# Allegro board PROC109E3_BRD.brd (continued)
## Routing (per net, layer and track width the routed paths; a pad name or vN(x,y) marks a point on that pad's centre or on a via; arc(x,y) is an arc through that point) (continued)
PRG1_IEP0_EDC_LATCH_IN0: length 33.4
  TOP w0.102: U18.Y4 86.67,27.08 87.14,27.08 87.58,26.65 87.58,26.64 87.74,26.49
  TOP w0.135: v1(98.73,24.18) 98.15,24.77 89.46,24.77 89.42,24.8 87.74,26.49
  BOTTOM w0.135: v1(98.73,24.18) 98.47,23.92 98.47,19.39 99.01,18.85 109.02,18.85 J5.8
PRG1_IEP0_EDC_LATCH_IN1: length 53.4
  TOP w0.102: v2(85.93,32.38) 85.41,31.86 U18.V13
  L03_SIG1 w0.102: v2(85.93,32.38) 86.65,32.38 87.44,33.17 87.74,33.17
  L03_SIG1 w0.121: 87.74,33.17 98.72,33.17 100.65,31.24 104.39,31.24 105.35,32.2 105.38,32.2 105.63,32.45 105.63,32.48 108.51,35.35 114.45,35.35 v1(114.88,35.79)
  BOTTOM w0.135: J5.12 116.95,18.49 114.88,20.55 v1(114.88,35.79)
PRG1_IEP0_EDC_SYNC_OUT0: length 33.5
  TOP w0.102: v2(85.36,26.82) 85.31,26.86 U18.U3
  L03_SIG1 w0.121: v2(85.36,26.82) 85.89,26.29 87.71,26.29 88.32,25.68 v1(98.73,25.68)
  BOTTOM w0.135: v1(98.73,25.68) 98.2,25.15 98.2,19.12 99.01,18.31 100.15,18.31 101.04,17.42 107.9,17.42 J5.6
PRG1_IEP0_EDC_SYNC_OUT1: length 36.2
  TOP w0.102: U18.T2 84.11,26.08 84.11,25.64 84.41,25.34 84.41,25.02
  TOP w0.135: 84.41,25.02 84.41,24.81 86.44,22.78 86.44,21.46 88.29,19.61 v1(99.01,19.61)
  BOTTOM w0.135: J5.10 110.8,19.61 v1(99.01,19.61)
PRG1_MDIO0_MDC: length 102.9
  TOP w0.102: U18.W1 86.23,25.53
  TOP w0.135: U7.42 139.68,43.77 v1(139.67,43.76) ; 86.23,25.53 87.88,23.88 91.39,23.88 v1(91.92,23.34) ; U19.42 v1(139.68,24.62)
  L03_SIG1 w0.121: v1(139.68,24.62) 142.04,26.97 142.04,31.04 141.4,31.67 138.18,31.67 137.69,31.19 137.69,25.73 138.61,24.82 138.61,21.01 137.72,20.12 133.08,20.12 132.02,21.18 100.07,21.18 97.48,23.77 92.35,23.77 v1(91.92,23.34)
  BOTTOM w0.135: v1(139.67,43.76) 139.99,43.45 139.99,42.38 139.52,41.91 138.66,41.91 136.42,39.67 136.42,27.88 v1(139.68,24.62)
PRG1_MDIO0_MDIO: length 88.5
  TOP w0.102: U18.V2 85.39,25.45 85.41,25.44
  TOP w0.114: 85.83,25.02 85.41,25.44
  TOP w0.135: R135.2 139.44,23.4 v1(139.42,23.42) 139.18,23.66 U19.41 ; v1(89.74,22.86) 87.99,22.86 85.83,25.02 ; v1(139.42,42.65) 139.42,43.09 139.18,43.33 U7.41
  L03_SIG1 w0.121: v1(89.74,22.86) 90.47,22.12 91.87,22.12 92.42,22.68 97.85,22.68 100.45,20.07 111.82,20.07 112.27,20.52 131.72,20.52 132.74,19.51 138.07,19.51 139.42,20.85 v1(139.42,23.42)
  BOTTOM w0.135: v1(139.42,23.42) 136.15,26.69 136.15,39.78 139.01,42.65 v1(139.42,42.65)
PRG1_RGMII1_RD0: length 25.9
  TOP w0.102: v2(85.93,26.82) 85.93,26.82 85.93,26.82 U18.V4
  L03_SIG1 w0.121: v1(100.63,26.01) 101.08,26.01 101.19,25.89 101.19,25.55 101.07,25.43 99.8,25.43 99.11,26.11 88.52,26.11 87.81,26.82 v2(85.93,26.82)
  BOTTOM w0.135: v1(100.63,26.01) 100.63,25.41 100.85,25.2 101.47,25.2 101.68,25.41 101.68,26.06 104.45,28.84 U40.29
PRG1_RGMII1_RD1: length 25.9
  TOP w0.102: v2(85.93,27.38) 85.89,27.41 U18.W5
  L03_SIG1 w0.121: v1(102.59,25.86) 103.56,24.89 103.56,24.61 103.25,24.31 102.92,24.31 101.96,25.27 101.96,25.65 101.18,26.43 88.95,26.43 88.92,26.47 88.77,26.47 87.82,27.38 v2(85.93,27.38)
  BOTTOM w0.135: U40.27 104.57,27.84 v1(102.59,25.86)
PRG1_RGMII1_RD2: length 25.9
  TOP w0.102: 87.74,26.87 87.24,27.36 U18.AA4
  TOP w0.135: 87.74,26.87 89.54,25.07 103.66,25.07 103.89,24.84 103.89,24.03 103.62,23.76 102.7,23.76 v1(102.26,24.21)
  BOTTOM w0.135: v1(102.26,24.21) 104.89,26.84 U40.25
PRG1_RGMII1_RD3: length 25.9
  TOP w0.102: U18.Y5 86.67,28.14 87.23,28.14 87.56,27.81
  TOP w0.135: 87.56,27.81 89.64,25.73 96.52,25.73 97.23,26.44 106.27,26.44 106.4,26.31 106.4,24.9 106.27,24.77 105.54,24.77 105.32,24.99 v1(105.32,25.84)
  BOTTOM w0.135: U40.23 v1(105.32,25.84)
PRG1_RGMII1_RX_CTL: length 25.9
  TOP w0.102: 87.74,27.25 87.13,27.86 U18.AA5
  TOP w0.135: v1(105.21,24.18) 104.04,25.35 100.23,25.35 99.47,26.11 97.66,26.11 96.95,25.4 89.59,25.4 87.74,27.25
  BOTTOM w0.135: U40.21 107.25,24.07 106.17,22.99 104.78,22.99 104.65,23.12 104.65,24.07 104.76,24.18 v1(105.21,24.18)
PRG1_RGMII1_RXC: length 26
  TOP w0.102: 87.74,25.6 87.17,26.16 87.17,26.48 87.01,26.64 86.67,26.64 U18.Y2
  TOP w0.135: 87.74,25.6 89.18,24.16 96.49,24.16 97.66,22.99 102.97,22.99 v1(103.68,22.28)
  BOTTOM w0.135: v1(103.68,22.28) 104.17,21.79 106.07,21.79 108.25,23.97 U40.19
PRG1_RGMII1_TD0: length 37.6
  TOP w0.102: U18.V5 84.98,27.86 v2(84.93,27.91)
  L03_SIG1 w0.121: v1(98.76,27.37) 98.57,27.55 88.76,27.55 88.14,28.16 85.19,28.16 v2(84.93,27.91)
  BOTTOM w0.135: U40.41 108.25,34.48 106.35,36.37 105.99,36.37 104.9,37.47 103.2,37.47 99.49,33.76 99.49,31.61 99.36,31.47 98.51,31.47 98.37,31.34 98.37,31.07 98.51,30.93 99.36,30.93 99.49,30.8 99.49,30.53 99.36,30.4 98.51,30.4 98.37,30.26 98.37,29.99 98.51,29.86 99.35,29.86 99.59,29.62 99.59,28.21 v1(98.76,27.37)
PRG1_RGMII1_TD1: length 37.7
  TOP w0.102: 86.21,25.02 85.61,25.61 85.61,26.08 U18.W2
  TOP w0.135: v1(100.56,22.3) 100.24,22.62 91.73,22.62 90.75,23.6 87.63,23.6 86.64,24.59 86.64,24.59 86.21,25.02
  BOTTOM w0.135: U40.39 107.25,34.29 107.24,34.29 105.92,35.61 102.06,35.61 101.13,34.68 101.13,33.69 100.1,32.66 100.1,22.76 v1(100.56,22.3)
PRG1_RGMII1_TD2: length 37.6
  TOP w0.102: U18.V6 85.39,28.78 v2(85.36,28.82)
  L03_SIG1 w0.121: v2(85.36,28.82) 85.73,28.45 88.34,28.45 88.98,27.81 100.24,27.81 v1(100.63,27.41)
  BOTTOM w0.135: v1(100.63,27.41) 101.22,27.41 101.38,27.57 101.38,27.98 101.17,28.19 100.61,28.19 100.47,28.33 100.47,28.6 100.61,28.73 101.21,28.73 101.35,28.87 101.35,29.14 101.21,29.27 100.61,29.27 100.47,29.4 100.47,29.67 100.61,29.81 101.06,29.81 101.19,29.94 101.19,30.21 101.06,30.35 100.61,30.35 100.47,30.48 100.47,30.75 100.61,30.89 101.21,30.89 101.35,31.02 101.35,31.29 101.21,31.42 100.61,31.42 100.47,31.56 100.47,31.83 100.61,31.96 101.21,31.96 101.4,32.15 101.4,34.54 101.9,35.05 104.27,35.05 104.73,34.59 104.92,34.59 105.5,35.16 105.77,35.16 105.94,34.98 105.94,34.72 105.18,33.96 105.18,33.77 105.61,33.34 U40.38
PRG1_RGMII1_TD3: length 37.7
  TOP w0.102: U18.AA7 87.65,28.86 87.74,28.77
  TOP w0.135: 87.74,28.77 89.84,26.67 95.68,26.67 97.22,28.2 102.04,28.2 103.3,29.46 103.3,30.02 105.23,31.95 106.17,31.95 106.83,31.29 106.83,29.59 107.14,29.29 109.73,29.29 110.08,29.64 110.08,31.7 109.73,32.05 106.73,32.05 106.16,32.62 v1(105.21,32.62)
  BOTTOM w0.135: v1(105.21,32.62) 105.21,32.36 105.36,32.21 105.61,32.21 105.74,32.34 U40.36
PRG1_RGMII1_TX_CTL: length 37.6
  TOP w0.102: 87.74,28.39 87.57,28.56 86.69,28.56 U18.Y7
  TOP w0.135: 87.74,28.39 89.79,26.34 95.96,26.34 97.54,27.91 102.41,27.91 103.26,27.07 106.37,27.07 106.56,27.26 106.56,27.63 106.43,27.76 104.71,27.76 104.52,27.95 104.52,28.19 104.66,28.33 106.43,28.33 106.56,28.46 106.56,28.7 106.4,28.86 104.73,28.86 104.6,29 104.6,29.24 104.73,29.38 106.43,29.38 106.56,29.51 106.56,29.78 106.43,29.92 105.39,29.92 105.26,30.05 105.26,30.32 105.39,30.45 106.16,30.45 106.3,30.59 106.3,31.2 106.16,31.34 v1(105.32,31.34)
  BOTTOM w0.135: U40.34 v1(105.32,31.34)
PRG1_RGMII1_TXC: length 30.7
  L03_SIG1 w0.121: v1(92.38,27.13) 92.82,27.13 93,26.94 101.71,26.94 102.03,26.62 103.2,26.62 103.34,26.77 103.34,26.94 102.95,27.33 v1(102.11,27.33)
  BOTTOM w0.135: R286.2 90.06,24.5 90.35,24.21 92.41,24.21 93.17,24.97 93.17,26.34 v1(92.38,27.13) ; v1(102.11,27.33) 101.79,27.65 101.79,28.08 101.93,28.22 102.91,28.22 103.05,28.35 103.05,28.69 102.91,28.82 101.93,28.82 101.79,28.96 101.79,29.53 102.74,30.48 104.9,30.48 105.05,30.34 U40.32
PRG_CPSW_RGMII1_MUX_SEL: length 49.5
  TOP w0.102: 87.2,36.7 86.73,36.24 86.37,36.24 86.11,35.98 86.11,35.64 U18.Y20
  TOP w0.135: R62.1 97.34,43.87 v1(97.33,43.87) 96.76,43.87 94.2,41.3 91.8,41.3 87.2,36.7
  L03_SIG1 w0.121: v1(110.36,41.57) 109.97,41.17 107.93,41.17 105.15,43.94 97.41,43.94 v1(97.33,43.87)
  BOTTOM w0.135: U40.10 110.49,28.84 110.74,29.08 110.74,29.08 ; U40.9 110.49,29.34 110.74,29.08 ; 110.74,29.08 111.05,29.08 111.43,28.7 R250.2 112.03,29.1 112.24,29.31 112.95,29.31 113.47,29.82 113.47,34.36 110.36,37.47 v1(110.36,41.57)
QSPI_RST_N: length 3.7
  TOP w0.135: U2.3 78.51,49.28 v1(78.49,49.25)
  BOTTOM w0.135: v1(78.49,49.25) 77.64,49.25 U31.4
R_BP_CONN_1_PORZ: length 3
  TOP w0.135: R4.1 R8.2 27.78,57.12 27.94,57.29 U1.3
R_BP_CONN_2_PORZ: length 3.2
  TOP w0.135: R2.2 R3.1 U1.6
SENCE3_IP: length 4
  BOTTOM w0.135: U27.8 20.24,54.08 21.37,52.95 R188.2
SOC_ADC0_AIN0: length 62.4
  TOP w0.102: 80.39,36.7 U18.H21
  TOP w0.135: R142.1 R143.2 43.65,20.78 45.17,22.3 51.59,22.3 v1(52.78,23.49) ; 80.39,36.7 80.39,38.5 79.96,38.94 79.96,43.05 78.11,44.91 72.39,44.91 71.56,44.08 67.73,44.08 67.21,43.56 64.41,43.56 63.63,42.77 v1(63.63,41.76) 63.63,41.1 C28.1
  BOTTOM w0.135: v1(52.78,23.49) 55.41,26.12 55.41,34.98 62.18,41.76 v1(63.63,41.76)
SOC_ADC0_AIN1: length 48.1
  TOP w0.102: U18.F19 79.79,34.86 v2(79.83,34.89)
  TOP w0.135: v1(58.72,23.39) 57.84,22.51 57.84,21.26 57.37,20.78 R153.1 R152.2
  L03_SIG1 w0.102: 79.83,35.39 v2(79.83,34.89)
  L03_SIG1 w0.121: 79.83,35.39 79.38,35.84 79.38,37.3 77.83,38.84 74.27,38.84 73.65,39.47 73.65,40.03 72.03,41.66 v1(69.14,41.66)
  BOTTOM w0.135: v1(58.72,23.39) 58.72,24.08 60.78,26.14 60.78,29.72 61.33,30.26 61.33,39 61.87,39.54 66.21,39.54 68.33,41.66 v1(69.14,41.66) 70.62,43.13 C118.1
SOC_ADC0_AIN2: length 59.1
  TOP w0.102: U18.F21 79.2,36.06 79.2,36.1 78.7,36.6 78.7,36.7
  TOP w0.135: v1(67.87,42.34) 68.53,43 72.36,43 73.19,43.83 77.66,43.83 78.7,42.78 78.7,36.7 ; R144.2 R145.1 46.39,20.78 47.58,21.97 52.55,21.97 v1(53.85,23.27)
  BOTTOM w0.135: C110.1 67.61,43.05 67.87,42.79 v1(67.87,42.34) 66.31,40.78 62.35,40.78 59.94,38.38 59.94,37.29 59.51,36.86 59.51,26.76 56.83,24.08 56.41,24.08 55.28,22.95 54.17,22.95 v1(53.85,23.27)
SOC_ADC0_AIN3: length 56.6
  TOP w0.102: 78.97,36.7 78.97,36.68 79.67,35.98 79.67,35.64 U18.F20
  TOP w0.135: R146.2 R147.1 49.14,20.78 50.05,21.7 53.22,21.7 v1(54.91,23.39) ; v1(66.27,42.52) 67.36,42.52 68.11,43.27 72,43.27 72.83,44.1 77.77,44.1 78.97,42.9 78.97,36.7
  BOTTOM w0.135: C108.1 66.11,42.68 v1(66.27,42.52) 66.27,42.44 64.88,41.05 62.24,41.05 58.22,37.03 58.22,26.7 v1(54.91,23.39)
SOC_ADC0_AIN4: length 64.1
  TOP w0.102: U18.H20 80.08,35.68 80.08,36.3 79.68,36.7
  TOP w0.135: R148.2 R149.1 51.88,20.78 52.51,21.41 54.01,21.41 55.99,23.39 v1(56.44,23.39) ; 79.68,36.7 79.53,36.86 79.53,37.01 79.53,43.1 77.99,44.64 72.5,44.64 71.67,43.81 67.84,43.81 67.31,43.28 64.68,43.28 64.26,42.87 v1(64.26,42.42) 64.26,41.94 65.14,41.05 C33.1
  BOTTOM w0.135: v1(56.44,23.39) 55.63,22.58 52.76,22.58 52.2,23.14 52.2,24.08 52.76,24.64 52.76,32.71 62.46,42.42 v1(64.26,42.42)
SOC_ADC0_AIN5: length 50.5
  TOP w0.102: 78.44,36.7 78.44,36.58 78.89,36.12 U18.E21
  TOP w0.135: R150.2 R151.1 54.62,20.78 55.99,22.15 56.72,22.15 57.45,22.89 v1(57.45,23.39) ; v1(68.86,42.57) 72.42,42.57 73.41,43.56 77.55,43.56 78.44,42.67 78.44,36.7
  BOTTOM w0.135: C117.1 69.11,42.82 v1(68.86,42.57) 66.8,40.51 62.46,40.51 61.06,39.11 61.06,30.65 60.5,30.1 60.5,26.44 v1(57.45,23.39)
SOC_ADC0_AIN6: length 58.2
  TOP w0.102: U18.G20 79.88,35.38 79.88,36.1 79.27,36.7
  TOP w0.135: 79.27,36.7 79.24,36.73 79.24,43.01 77.88,44.37 72.61,44.37 71.79,43.54 67.95,43.54 67.41,43 65.77,43 65.28,42.51 v1(65.28,42.06) 65.82,41.52 66.18,41.52 66.65,41.05 C35.1 ; R154.2 R155.1 60.3,21.01 60.3,22.73 58.57,24.46 v1(54.97,24.46)
  BOTTOM w0.135: v1(65.28,42.06) 64.54,41.33 62.13,41.33 55.68,34.87 55.68,25.17 v1(54.97,24.46)
SOC_ADC0_AIN7: length 51.7
  TOP w0.102: 78.16,36.7 78.16,36.57 78.58,36.15 78.58,35.68 U18.E20
  TOP w0.135: C36.1 69.37,41.05 v1(70.43,42.11) 72.67,42.11 73.85,43.29 77.44,43.29 78.16,42.56 78.16,36.71 78.16,36.7 ; v1(59.99,24.64) 60.91,24.64 63.22,22.33 63.22,21.19 R157.1 R156.2
  BOTTOM w0.135: v1(70.43,42.11) 70.12,41.8 69.94,41.8 67.41,39.27 61.98,39.27 61.6,38.89 61.6,37.24 62.36,36.48 62.36,30.35 61.77,29.77 61.77,26.42 v1(59.99,24.64)
SOC_CLKIN: length 5.6
  TOP w0.102: U18.D20 78.38,35.38 78.38,36.06 77.8,36.64 77.8,36.7
  TOP w0.135: 77.8,36.7 77.24,37.26 77.24,39.67 77.42,39.86 U11.4
SOC_CLKIN_BUFF: length 66.2
  TOP w0.135: v1(76.12,41.02) U11.2 ; R46.2 v1(115.27,47.37)
  L03_SIG1 w0.121: v1(76.12,41.02) 76.12,42.66 70.14,48.65 70.14,49.53 70.39,49.78 71.76,49.78 72.44,49.1 77.34,49.1 77.61,48.83 79.15,48.83 79.65,49.33 82.04,49.33 83.59,47.77 83.59,47.19 85.75,45.03 87.28,45.03 88.01,44.3 88.01,43.77 88.34,43.44 90.14,43.44 90.99,44.29 91.54,44.29 91.87,43.96 91.87,43.87 92.56,43.19 93.12,43.19 93.57,43.64 93.57,44.2 93.92,44.54 96.69,44.54 97.94,45.79 104.7,45.79 106.93,43.57 109.95,43.57 112.95,46.57 114.46,46.57 v1(115.27,47.37)
SOC_CLKIN_BUFF_R: length 2.6
  TOP w0.135: R46.1 116.93,47.96 117.16,48.19 U6.3
SOC_CPSW_RGMII1_TXC: length 1.5
  TOP w0.102: v2(85.93,31.32) 85.93,31.83 U18.W13
  BOTTOM w0.135: R287.1 86.21,31.04 v2(85.93,31.32)
SOC_EMU0: length 58.5
  TOP w0.102: U18.C5 77.89,27.41 v2(77.86,27.38)
  TOP w0.135: U16.5 28.79,35.14 29.69,34.24 29.69,33.27 30.76,32.21 v1(31.39,32.21)
  L03_SIG1 w0.121: v2(77.86,27.38) 74.67,24.19 73.37,24.19 71.59,25.96 69.42,25.96 66.85,28.53 65.92,28.53 65.18,29.27 65.18,30.32 63.84,31.66 44.99,31.66 44.2,30.86 39.15,30.86 38.35,31.66 37.25,31.66 36.7,32.21 v1(31.39,32.21)
SOC_EMU1: length 66
  TOP w0.102: U18.B3 77.11,27.14 76.77,27.14
  TOP w0.114: 76.77,27.14 76.34,26.71 76.34,25.97 76.05,25.68
  TOP w0.135: v1(32,35.53) 31.61,35.14 U16.4 ; 76.05,25.68 73.92,23.55 73.92,20.02 v1(73.56,19.66)
  L03_SIG1 w0.121: v1(73.56,19.66) 73.56,21.89 72.06,23.39 72.06,24.43 70.79,25.7 69.27,25.7 66.69,28.28 65.81,28.28 64.9,29.19 64.9,30.24 63.74,31.4 45.24,31.4 44.2,30.35 39.15,30.35 38.1,31.4 37.13,31.4 36.79,31.74 31.2,31.74 30.89,32.05 30.89,34.42 v1(32,35.53)
SOC_I2C0_SCL: length 223.6
  TOP w0.135: U17.6 64.69,35.84 65.48,36.63 66.75,36.63 v1(67.21,36.17) 67.84,35.53 R93.1 ; v1(147.02,19.86) 146.3,20.57 R141.1
  L03_SIG1 w0.121: v1(67.21,36.17) 67.21,37.48 65.17,39.52 62.79,39.52 61.32,41 57,41 54.33,43.66 45.87,43.66 45.21,44.32 42.07,44.32 41.64,43.89 39.04,43.89 v1(38.05,44.88) ; v1(147.02,19.86) 147.02,20.3 153.75,27.04 v1(153.75,41.27) 153.75,48.96 v1(156.82,52.03)
  BOTTOM w0.135: R237.2 67.23,36.2 v1(67.21,36.17) ; v1(38.05,44.88) 38.05,45.7 37.52,46.23 37.52,47.85 40.44,50.77 40.44,53.09 38.66,54.86 38.66,59.64 40.06,61.04 71.71,61.04 74.35,58.4 82.48,58.4 83.61,59.54 83.61,60.33 86.06,62.78 136.69,62.78 147.43,52.03 v1(156.82,52.03) ; U35.15 v1(153.75,41.27)
SOC_I2C0_SCL_BP: length 27.8
  TOP w0.135: J5.17 125.78,14.67 129.32,14.67 132.2,11.79 139.93,11.79 141.78,13.64 141.78,14.91 143.43,16.56 143.43,19.4 144.57,20.54 R141.2
SOC_I2C0_SCL_RC: length 9.2
  TOP w0.102: U18.B16 77.38,33.38 76.23,33.38 76.16,33.44 76.05,33.44
  TOP w0.135: R93.2 C47.1 69.94,34.12 70.18,33.88 72.85,33.88 73.29,33.44 76.05,33.44
SOC_I2C0_SDA: length 228
  TOP w0.135: R97.1 68.96,32.68 67.49,34.15 67.49,35.05 66.37,36.17 v1(65.91,36.17) 65.6,36.17 65.34,35.92 U17.5 ; R158.1 v1(146.23,19.08)
  L03_SIG1 w0.121: v1(158.8,51.28) 156.13,48.62 v1(156.13,41.27) 156.13,26.6 148.6,19.08 v1(146.23,19.08) ; v1(65.91,36.17) 65.91,38.42 65.06,39.27 62.59,39.27 61.27,40.59 56.82,40.59 55.04,42.37 39.4,42.37 v1(37.91,43.86)
  BOTTOM w0.135: v1(65.91,36.17) R238.2 ; v1(37.91,43.86) 38.48,44.42 38.48,45.92 37.8,46.61 37.8,47.75 40.74,50.7 40.74,53.4 38.93,55.22 38.93,59.4 40.3,60.77 71.55,60.77 74.19,58.14 82.62,58.14 83.88,59.4 83.88,60.22 86.18,62.51 136.5,62.51 147.73,51.28 v1(158.8,51.28) ; U35.2 v1(156.13,41.27)
SOC_I2C0_SDA_BP: length 24.8
  TOP w0.135: R158.2 144.52,17.04 143.16,15.67 143.16,12.7 141.36,10.9 129.67,10.9 J5.19
SOC_I2C0_SDA_RC: length 9.9
  TOP w0.102: U18.B15 77.08,33.17 76.05,33.17
  TOP w0.135: v1(70.03,33.41) 70.03,33.41 69.94,33.32 R97.2 70.22,32.36 70.69,32.36 71.88,33.55 72.79,33.55 73.17,33.17 76.05,33.17
  BOTTOM w0.135: v1(70.03,33.41) 70.03,33.43 70.04,33.43 C161.1
SOC_I2C1_SCL: length 135.5
  TOP w0.102: U18.A17 76.7,34.06 76.07,34.06 76.05,34.04
  TOP w0.135: R88.2 v1(69.55,37.11) 69.9,36.75 70.08,36.75 72.06,34.77 72.09,34.77 72.1,34.76 72.91,34.76 73.63,34.04 76.05,34.04 ; v1(42.72,35.59) 41.81,34.67 41.81,22.12 39.17,19.48 39.17,12.17 39.89,11.45 59.05,11.45 J1.17 ; U9.2 8.08,44.51 v1(7.42,45.16)
  L03_SIG1 w0.121: v1(69.55,37.11) 69.55,35.92 69.01,35.38 64.83,35.38 62.88,37.33 62.03,37.33 61.19,38.18 58.1,38.18 57.33,37.41 57.33,34.62 56.87,34.16 56.03,34.16 55.45,34.75 55.45,35.41 54.66,36.19 43.33,36.19 v1(42.72,35.59) 42.04,35.59 39.65,37.97 39.65,39.59 36.58,42.66 32.55,42.66 31.15,41.26 27.53,41.26 26.41,42.37 19.13,42.37 18.82,42.06 10.52,42.06 v1(7.42,45.16)
SOC_I2C1_SDA: length 138.9
  TOP w0.102: 76.05,34.64 77.11,34.64 U18.B18
  TOP w0.135: J1.19 61.32,11.18 39.78,11.18 38.86,12.09 38.86,19.69 41.38,22.2 41.38,35.13 v1(42.77,36.53) ; U9.3 8.34,45.16 v1(8.34,45.16) ; 76.05,34.64 75.77,34.64 75.11,35.31 72.29,35.31 70.33,37.26 70.33,37.44 70,37.77 70,38.1 v1(69.6,38.51) R82.2
  L03_SIG1 w0.121: v1(69.6,38.51) 69.09,38 69.09,35.97 68.78,35.66 64.91,35.66 62.98,37.59 62.23,37.59 61.39,38.43 57.99,38.43 56.97,37.41 56.97,34.7 56.78,34.5 56.05,34.5 55.73,34.83 55.73,35.56 54.76,36.53 v1(42.77,36.53) 41.76,36.53 40.06,38.23 40.06,39.55 36.68,42.92 32.28,42.92 30.87,41.51 27.63,41.51 26.52,42.63 18.93,42.63 18.64,42.34 13.11,42.34 11.94,43.51 9.99,43.51 v1(8.34,45.16)
SOC_I2C1_TA_SCL: length 15.2
  TOP w0.135: U9.7 6.11,44.51 8,46.4 8.17,46.4 9.33,47.56 9.33,48.11 9.33,52.14 v1(9.3,52.17)
  BOTTOM w0.135: R187.2 v1(9.3,52.17) 9.01,52.45 J15.36
SOC_I2C1_TA_SDA: length 17
  TOP w0.135: v1(9.45,54.05) 8.76,53.37 8.76,51.26 9.06,50.96 9.06,48.22 9.06,48.22 9.06,47.77 8.03,46.74 7.69,46.74 6.11,45.16 U9.6
  BOTTOM w0.135: J15.38 7.56,53.45 8.15,54.05 v1(9.45,54.05) R182.2
SOC_PRG1_RGMII1_TXC: length 4.6
  TOP w0.102: v2(85.93,28.82) 85.93,28.39 U18.W6
  BOTTOM w0.135: v2(85.93,28.82) 85.93,28.37 87.43,26.87 R286.1
SOC_RESET_REQZ: length 22.6
  TOP w0.102: U18.C17 77.89,34.28 v2(77.86,34.33)
  TOP w0.135: U13.2 59.26,37.56 v1(59.44,37.39) 59.44,36.37 TP24.1
  L03_SIG1 w0.121: v1(59.44,37.39) 59.75,37.08 62.77,37.08 64.78,35.07 71.07,35.07 71.09,35.05 77.14,35.05 v2(77.86,34.33)
SOC_RESETSTATZ: length 15.9
  TOP w0.102: U18.E19 78.47,34.86 v2(78.44,34.89)
  TOP w0.135: v1(71.96,39.29) 71.96,39.74 71.7,40.01 TP13.1
  L03_SIG1 w0.121: v1(71.96,39.29) 71.96,38.3 71.53,37.87 70.62,37.87 70.37,37.62 70.37,36.77 71.09,36.05 73.91,36.05 74.19,36.33 77,36.33 v2(78.44,34.89)
  BOTTOM w0.135: v1(71.96,39.29) 71.7,39.29 71.14,39.86 R234.2
SOC_TCK: length 27.6
  TOP w0.102: v2(77.86,28.82) 77.89,28.78 U18.C6
  TOP w0.135: R162.1 70.31,15 69.79,14.48 67.51,14.48 67.12,14.87 67.12,18 67.32,18.2 67.32,24.22 67.13,24.4 67.13,24.99 69.29,27.15 v1(70.08,27.15)
  L03_SIG1 w0.121: v1(70.08,27.15) 70.8,27.87 71.85,27.87 73.05,26.67 75.03,26.67 77.18,28.82 v2(77.86,28.82)
SOC_TDI: length 17.1
  TOP w0.102: 76.05,25.25 76.55,25.75 76.55,26.52 U18.A3
  TOP w0.135: U25.5 70.69,16.16 71.57,15.28 72.93,15.28 74.19,16.53 74.19,23.38 76.05,25.25
SOC_TDO: length 1.8
  BOTTOM w0.135: U42.2 68.49,20.57 69.13,19.94 R271.1
SOC_TMS: length 17.1
  TOP w0.114: U18.B4 76.68,27.36 76.1,26.77
  TOP w0.135: U25.6 71.34,16.14 71.93,15.55 72.82,15.55 73.1,15.82 73.1,20.02 73.65,20.56 73.65,23.66 76.1,26.11 76.1,26.77
SOC_TRST#: length 22
  TOP w0.102: 76.05,28.24 76.08,28.27 76.3,28.27 76.67,28.64 77.11,28.64 U18.B6
  TOP w0.135: 76.05,28.24 75.23,28.24 73.91,26.92 72.96,26.92 R120.2 72.71,26.25 72.47,26.01 68.58,26.01 67.42,24.85 67.42,24.5 67.59,24.33 67.59,21.82 69.34,20.07 70.61,20.07 71.99,18.69 U25.7
SPI0_CLK: length 73.8
  TOP w0.102: 76.05,28.86 76.31,28.86 76.52,29.07 77.1,29.07 U18.B8
  TOP w0.135: 76.05,28.86 74.99,28.86 74.19,28.07 71.28,28.07 71.19,27.98 69.36,27.98 69.34,27.97 66.5,25.12 v1(66.5,23.06)
  L03_SIG1 w0.121: v1(66.5,23.06) 68.02,23.06 69,22.08 69,20.94 74.43,15.51 86.99,15.51 87.13,15.36 89.57,12.92 99.11,12.92 100.35,11.68 117.71,11.68 J5.13
SPI0_CS1: length 168.1
  TOP w0.102: 76.05,28.59 76.07,28.58 76.32,28.58 76.61,28.86 U18.B7
  TOP w0.135: 76.05,28.59 75.2,28.59 73.8,27.19 73.22,27.19 72.7,27.71 69.47,27.71 66.85,25.1 66.85,24.1 67.05,23.91 67.05,18.31 66.85,18.11 66.85,14.76 67.51,14.1 77.9,14.1 78.85,15.05 82.49,15.05 85.82,11.72 95.72,11.72 96.24,11.2 99.24,11.2 100.86,9.58 v1(127.86,9.58)
  L03_SIG1 w0.121: v1(127.89,19.23) v1(114.63,19.23)
  BOTTOM w0.135: v1(114.63,19.23) 114.2,18.8 113.28,18.8 112.43,19.65 112.43,23.02 113.74,24.33 113.74,37.6 110.84,40.5 110.84,51.57 107.49,54.91 103.45,54.91 102.94,55.42 102.94,59.94 103.84,60.83 107.67,60.83 J6.6 ; v1(127.89,19.23) 128.21,18.91 128.21,18.89 128.29,18.8 128.29,16.53 128.32,16.5 128.32,12.96 128.29,12.93 128.29,10 v1(127.86,9.58)
SPI0_D0: length 104
  TOP w0.102: 76.05,29.13 76.29,29.13 76.52,29.36 U18.A8
  TOP w0.135: 76.05,29.13 74.88,29.13 74.08,28.33 71.16,28.33 71.08,28.25 69.24,28.25 69.19,28.19 68.83,27.84 v1(66.45,27.84)
  BOTTOM w0.135: v1(66.45,27.84) 65.66,28.63 65.66,32.69 69.04,36.07 69.04,39.19 69.88,40.04 69.88,40.55 72.54,43.21 72.54,44.68 71.53,45.7 68.3,45.7 63.38,50.62 63.38,53.73 66.66,57.01 82.6,57.01 83.04,57.01 84.96,58.93 84.96,59.77 86.62,61.43 114.7,61.43 J6.12
SPI0_D1: length 104.2
  TOP w0.102: v2(77.86,30.32) 77.89,30.28 U18.C9
  TOP w0.135: v1(61.93,34.85) 62.41,35.33 62.41,37.86 62.81,38.26 62.81,43.15 63.49,43.84 66.78,43.84 67.88,44.94 67.88,57.67 69.72,59.51 74.98,59.51 76.81,57.68 81.91,57.68 85.5,61.27 117.4,61.27 J6.14
  L03_SIG1 w0.121: v1(61.93,34.85) 62.89,34.85 64.34,33.4 66.49,33.4 67.18,32.7 67.18,29.64 68.26,28.56 75.32,28.56 77.08,30.32 v2(77.86,30.32)
SPI3_CLK: length 44.4
  TOP w0.102: U18.N3 83.32,26.86 v2(83.37,26.82)
  L03_SIG1 w0.121: v2(83.37,26.82) 83.37,25.47 85.14,23.7 85.14,21.23 86.82,19.56 v1(86.82,18.57)
  BOTTOM w0.135: v1(86.82,18.57) 83.84,15.59 78.38,15.59 76.24,13.46 67.44,13.46 65.93,11.95 57.5,11.95 J1.13
SPI3_CS0: length 87
  TOP w0.102: 78.53,25.02 78.63,25.12 78.63,25.6 U18.E1
  TOP w0.135: 78.53,25.02 78.53,25.01 77,23.48 76.69,23.48 76.17,22.96 v1(76.17,16.21)
  BOTTOM w0.135: v1(76.17,16.21) 74.32,14.36 67.4,14.36 64.2,17.57 49.97,17.57 44.22,23.32 44.22,23.69 44.22,33.73 46.23,35.73 46.23,37.03 47.37,38.17 47.37,40.29 48.32,41.24 48.32,49.74 44.55,53.52 44.55,57.91 J2.6
SPI3_CS1: length 91.7
  TOP w0.102: v2(83.37,27.38) 83.35,27.36 U18.N4
  L03_SIG1 w0.121: v1(84.81,19.23) 84.1,19.94 84.1,24.28 82.85,25.53 82.85,26.87 v2(83.37,27.38)
  BOTTOM w0.135: v1(84.81,19.23) 82.14,19.23 81.53,18.62 81.2,18.62 80.96,18.86 80.43,18.86 79.97,18.4 74.11,18.4 73.1,17.4 66.69,17.4 64.91,19.18 63.75,19.18 62.86,20.07 51.1,20.07 47.4,23.77 47.4,32.26 47.4,32.26 47.4,33.17 49.68,35.45 49.68,35.71 56.15,42.18 56.15,50.79 59.79,54.43 59.79,57.91 J2.18
SPI3_D0: length 93.3
  TOP w0.102: U18.N1 83.17,25.59 83.17,25.02
  TOP w0.135: v1(85.81,18.33) 86.23,18.76 86.23,19.48 83.69,22.02 83.69,24 83.17,24.53 83.17,25.02
  BOTTOM w0.135: J2.12 52.17,57.91 52.17,53.01 49.72,50.56 49.72,38.77 48.23,37.28 48.23,36.93 44.94,33.64 44.94,24.65 51.49,18.11 64.46,18.11 66.31,16.26 69,16.26 69.97,15.29 73.1,15.29 74.79,16.98 77.69,16.98 78.05,17.35 81.03,17.35 82.16,18.48 85.66,18.48 v1(85.81,18.33)
SPI3_D1: length 92.4
  TOP w0.102: 82.9,25.02 82.9,25.31 82.61,25.59 82.61,26.08 U18.N2
  TOP w0.135: 82.9,25.02 82.9,24.42 83.41,23.9 83.41,21.56 v1(85.73,19.25)
  BOTTOM w0.135: v1(85.73,19.25) 85.24,18.76 82.06,18.76 80.91,17.62 77.94,17.62 77.57,17.25 74.37,17.25 73.71,16.59 66.36,16.59 64.57,18.37 64.46,18.37 51.6,18.37 45.21,24.77 45.21,33.53 48.5,36.81 48.5,37.17 50.01,38.68 50.01,50.01 54.71,54.71 54.71,57.91 J2.14
SYNC1_OUT: length 92.6
  TOP w0.102: 76.05,34.36 U18.A18
  TOP w0.135: v1(67.67,10.79) 67.67,11.24 65.18,13.73 65.18,18.03 64.52,18.69 64.52,22.02 60.59,25.95 60.59,30.72 62.71,32.84 62.71,37.74 64.21,39.25 65.3,39.25 66.83,37.72 69.65,37.72 70.05,37.31 70.05,37.16 72.19,35.03 75.01,35.03 75.67,34.36 76.05,34.36
  BOTTOM w0.135: v1(67.67,10.79) 69.27,9.19 73.91,9.19 78.96,14.24 82.58,14.24 86.59,10.22 103.55,10.22 J5.3
SYNC2_OUT: length 106.4
  TOP w0.135: v1(144.42,9.19) 144.42,16.15 149.98,21.71 R140.2
  L03_SIG1 w0.121: J1.18 62.36,14.71 62.36,12.27 63.25,11.38 70.15,11.38 73.26,14.49 86.54,14.49 90.46,10.57 90.8,10.23 99.62,10.23 99.9,10.51 138.11,10.51 139.42,9.19 v1(144.42,9.19)
SYNC3_OUT: length 117.2
  TOP w0.135: v1(159.77,10.41) 159.77,19.48 160.87,20.59 R131.2
  L03_SIG1 w0.121: v1(159.77,10.41) 157.91,8.56 146.48,8.56 145.42,9.63 139.42,9.63 138.2,10.84 99.53,10.84 99.07,11.31 90.08,11.31 86.65,14.74 72.81,14.74 69.82,11.76 65.84,11.76 65.18,12.42 65.18,14.43 J1.20
SYS_BOOTMODE3: length 33.2
  TOP w0.135: R16.1 v1(13.84,51.82) 14.35,51.31 SW4.1 ; U4.3 28.14,51.15 27.97,51.32 27.97,51.37 v1(27.66,51.69)
  L03_SIG1 w0.121: v1(27.66,51.69) 22.3,51.69 22.17,51.82 v1(13.84,51.82)
  BOTTOM w0.135: v1(27.66,51.69) 27.66,50.7 28.17,50.19 28.96,50.19 29.87,51.1 29.87,56.41 28.96,57.33 26.06,57.33 25.57,56.84 U26.2
SYS_BOOTMODE4: length 28.3
  TOP w0.135: U4.4 v1(28.57,50.65) ; R27.1 v1(13.84,50.32) 14.12,50.04 SW4.2
  L03_SIG1 w0.121: v1(28.57,50.65) 26.57,50.65 26.24,50.32 v1(13.84,50.32)
  BOTTOM w0.135: U26.3 26.07,56.7 26.38,57.01 26.39,57.01 26.42,57.04 28.08,57.04 29.51,55.6 29.51,51.6 v1(28.57,50.65)
SYS_BOOTMODE5: length 33.3
  TOP w0.135: SW4.3 15.42,48.82 v1(13.84,48.82) R33.1 ; U4.5 27.82,50.15 27,50.98 27,51.8 27.96,52.76 v1(29.08,52.76)
  L03_SIG1 w0.121: v1(29.08,52.76) 29.08,50.39 28.78,50.09 28.09,50.09 27.85,50.33 26.63,50.33 26.21,49.91 14.93,49.91 v1(13.84,48.82)
  BOTTOM w0.135: U26.4 26.57,56.65 26.7,56.77 27.8,56.77 29.08,55.48 v1(29.08,52.76)
SYS_BOOTMODE6: length 27.5
  TOP w0.135: SW4.4 14.02,47.5 v1(13.84,47.32) R47.1 ; U4.6 v1(28.57,49.65)
  L03_SIG1 w0.121: v1(28.57,49.65) 27.99,49.65 27.58,50.07 26.78,50.07 26.29,49.58 22.52,49.58 22.48,49.58 17.45,49.58 15.19,47.32 v1(13.84,47.32)
  BOTTOM w0.135: v1(28.57,49.65) 28.12,49.65 27.22,50.55 27.22,51.87 28.73,53.37 28.73,54.92 28.39,55.26 U26.5
SYS_BOOTMODE7: length 26.2
  TOP w0.135: 29.37,49.15 27.82,49.15 v1(27.33,49.64) ; SW4.5 14.25,46.23 v1(13.84,45.82) R52.1
  L03_SIG1 w0.121: v1(13.84,45.82) 14.28,45.82 17.56,49.1 26.29,49.1 26.83,49.64 v1(27.33,49.64)
  BOTTOM w0.135: U26.7 28.19,54.26 28.45,54 28.45,53.47 26.92,51.95 26.92,50.05 v1(27.33,49.64)
SYS_BOOTMODE8: length 27.5
  TOP w0.135: SW4.6 14.48,44.96 v1(13.84,44.32) R66.1 ; v1(27.46,48.11) 28,48.65 U4.8
  L03_SIG1 w0.121: v1(13.84,44.32) 15.67,44.32 17.75,46.41 25.76,46.41 v1(27.46,48.11)
  BOTTOM w0.135: v1(27.46,48.11) 27.46,48.67 25.96,50.16 25.96,51.36 27.89,53.29 27.89,53.62 27.75,53.76 U26.8
SYS_BOOTMODE9: length 27.3
  TOP w0.135: U4.9 28.16,48.15 v1(27.23,47.22) ; R69.1 v1(13.84,42.82) 14.71,43.69 SW4.7
  L03_SIG1 w0.121: v1(27.23,47.22) 26.14,46.13 17.93,46.13 14.63,42.82 v1(13.84,42.82)
  BOTTOM w0.135: U26.9 26.57,52.37 25.65,51.45 25.65,49.96 26.9,48.72 26.9,47.55 v1(27.23,47.22)
TA_BOOTMODE_I2C_SCL: length 27.9
  TOP w0.135: v1(8.02,53.11) 7.59,53.54 7.59,55.88 11.61,59.89 15.47,59.89 19.14,56.23 21.69,56.23 24.31,53.61 v1(24.31,53.16)
  BOTTOM w0.135: J15.37 7.87,52.95 v1(8.02,53.11) R186.2 ; U26.12 24.41,53.06 v1(24.31,53.16)
TA_BOOTMODE_I2C_SDA: length 24.6
  TOP w0.135: v1(23.55,53.67) 21.26,55.96 19.02,55.96 15.36,59.62 11.72,59.62 8.02,55.93 v1(8.02,54.99)
  BOTTOM w0.135: v1(23.55,53.67) 23.63,53.76 U26.13 ; J15.39 7.45,53.95 8.02,54.53 v1(8.02,54.99) R178.2
TA_GPIO2: length 3.9
  TOP w0.135: v1(8.02,49.35) 7.46,48.79 TP6.1
  BOTTOM w0.135: J15.31 7.42,49.95 v1(8.02,49.35) R197.1
TA_GPIO3: length 43
  L03_SIG1 w0.121: v1(9.78,50.29) 10.4,50.29 11.48,51.37 11.48,53.54 15.62,57.68 25.38,57.68 25.94,57.12 31.06,57.12 31.72,57.79 35.81,57.79 36.43,57.17 TP3.1
  BOTTOM w0.135: J15.32 9.17,50.45 9.33,50.29 v1(9.78,50.29) R196.1 ; U28.1 36.97,52.38 36.43,52.93 TP3.1
TA_GPIO4: length 30.2
  TOP w0.135: v1(24.77,57.25) 23.5,57.25 21.67,59.08 16.66,59.08 15.58,60.16 11.5,60.16 6.58,55.24 6.58,52.68 v1(8.02,51.23)
  BOTTOM w0.135: R189.1 v1(8.02,51.23) 7.58,51.23 7.3,50.95 J15.33 ; U26.1 25.07,56.95 v1(24.77,57.25)
TA_PORZN: length 22.2
  TOP w0.135: v1(13.98,59.04) 11.57,59.04 10.72,58.19 10.72,55.85 11.35,55.23 11.35,47.48 v1(10.4,46.53)
  BOTTOM w0.135: Q8.3 v1(13.98,59.04) ; R211.1 v1(10.4,46.53) 8.29,46.53 6.87,47.95 J15.27
TA_POWERDOWN: length 44.6
  TOP w0.135: v1(8.05,39.04) 16.08,39.04 16.92,38.2 16.92,37.44 17.64,36.72 37.8,36.72 39.63,38.55 R84.1
  BOTTOM w0.135: J15.26 6.87,47.45 7.87,46.45 7.87,39.22 v1(8.05,39.04)
TA_PWR_EN: length 3.4
  BOTTOM w0.508: U41.3 3.36,29.52 R251.2
TA_SOC_INTN: length 122.1
  L03_SIG1 w0.121: v1(8.63,48.43) 5.15,48.43 2.46,45.75 2.46,29.72 5.49,26.7 7.87,26.7 8.33,26.24 8.33,24.97 7.44,24.08 7.44,23.7 6.38,22.63 6.38,19.58 7.39,18.57 10.64,18.57 12.01,19.94 12.01,21.13 13.39,22.5 13.39,23.55 16.1,26.26 22.23,26.26 22.73,25.76 22.73,22.43 31.04,14.12 31.04,9.24 31.59,8.69 38.05,8.69 39.09,9.73 65.02,9.73 v1(66.32,8.43)
  BOTTOM w0.135: J15.30 6.96,49.45 7.99,48.43 v1(8.63,48.43) 8.65,48.41 R202.1 ; Q16.3 66.12,8.63 v1(66.32,8.43)
TA_WARMRESETN: length 33.5
  TOP w0.135: v1(24.18,59.49) 23.86,59.8 21.81,59.8 21.41,59.41 16.72,59.41 15.69,60.43 11.26,60.43 6.2,55.37 6.2,48.62 7.34,47.47 v1(8.02,47.47)
  BOTTOM w0.135: J15.28 7.04,48.45 v1(8.02,47.47) R209.1 ; v1(24.18,59.49) 24.29,59.38 Q7.3
TCA6408_EXP_ADDR: length 2.1
  BOTTOM w0.135: U26.16 R177.2
TCA6408_EXP_INT: length 2.2
  BOTTOM w0.135: U26.11 25.57,52.32 24.94,51.69 R191.1
TEST_LED1_GREEN: length 118.9
  TOP w0.102: U18.U19 85.32,34.86 v2(85.35,34.89)
  L03_SIG1 w0.121: v1(100.61,56.31) 100.61,57.71 104.6,61.7 164.72,61.7 167.08,59.33 171.78,59.33 v1(172.27,59.83) ; v1(88.87,39.5) 88.37,39.5 87.93,39.06 87.93,38.19 85.35,35.62 v2(85.35,34.89)
  BOTTOM w0.135: v1(100.61,56.31) 100.61,50.44 100.94,50.11 100.94,45.59 98.93,43.59 98.93,41.91 97.31,40.29 96.42,40.29 94.05,37.91 91.37,37.91 89.79,39.5 v1(88.87,39.5) 88.56,39.81 88.56,41.44 89.31,42.19 89.31,44.15 88.61,44.85 R216.1 ; v1(172.27,59.83) R173.2 Q6.3
TEST_LED2_RED: length 157
  TOP w0.102: 76.05,29.4 76.27,29.4 76.44,29.57 76.6,29.57 U18.A9
  TOP w0.135: 76.05,29.4 74.66,29.4 73.87,28.6 71.05,28.6 70.97,28.52 69.13,28.52 69.11,28.5 68.94,28.32 66.73,28.32 v1(66.09,28.96)
  L03_SIG1 w0.121: v1(101.98,59.89) 104.04,61.95 165.4,61.95 v1(167.52,59.83)
  BOTTOM w0.135: v1(66.09,28.96) 66.09,32.74 70.05,36.7 70.05,37.79 70.15,37.9 70.15,40.44 72.87,43.16 72.87,44.73 71.64,45.97 68.41,45.97 63.65,50.73 63.65,53.61 66.78,56.74 82.49,56.74 83.15,56.74 84.69,58.28 85.23,58.82 85.23,59.66 86.73,61.16 100.71,61.16 v1(101.98,59.89) ; Q5.3 R172.2 v1(167.52,59.83)
TEST_LED3_RED: length 159.6
  TOP w0.102: U18.D1 78.39,25.26 78.16,25.02
  TOP w0.135: v1(160.38,8.87) 160.06,8.54 135.7,8.54 133.73,10.51 100.79,10.51 98.51,12.8 86.26,12.8 82.93,16.13 78.41,16.13 77.76,15.48 76.27,15.48 75.64,16.1 75.64,22.81 76.58,23.75 76.89,23.75 78.16,25.02
  L03_SIG1 w0.121: v1(171.96,57.63) 170.91,56.58 168.31,56.58 158.04,46.31 158.04,23.26 159.48,21.82 159.48,20.28 160.38,19.37 v1(160.38,8.87)
  BOTTOM w0.135: v1(171.96,57.63) 172.02,57.57 R174.2 174.92,57.57 Q9.3
TEST_LED4_GREEN: length 147.6
  TOP w0.102: U18.F3 79.81,26.86 v2(79.85,26.82)
  L03_SIG1 w0.121: v1(169.57,62.39) 172.4,62.39 173.27,61.53 173.27,59.58 170.87,57.18 168.45,57.18 157.63,46.36 157.63,21.84 157.8,21.67 157.8,19.42 156.21,17.83 144.72,17.83 142.85,15.96 140.37,15.96 138.48,17.86 132.26,17.86 131.44,18.67 98.02,18.67 96.82,17.48 81.86,17.48 81.33,18.01 79.76,18.01 78.89,18.88 78.89,22.78 79.04,22.94 79.04,26.01 v2(79.85,26.82)
  BOTTOM w0.135: R165.2 168.77,62.39 v1(169.57,62.39) 170.02,62.39 170.24,62.17 Q4.3
TIMER_IO0: length 58.9
  TOP w0.102: U18.K18 81.81,34.36 v2(81.84,34.33)
  TOP w0.135: v1(89.96,49.25) 90.81,49.25 91.39,49.84 93.48,49.84 93.92,50.28 93.92,51.42 94.05,51.55 95.94,51.55 96.07,51.69 96.07,53.65 95.94,53.78 95.67,53.78 95.53,53.65 95.53,52.22 95.4,52.09 95.13,52.09 94.99,52.22 94.99,53.65 94.86,53.78 94.59,53.78 94.46,53.65 94.46,52.22 94.32,52.09 94.05,52.09 93.92,52.22 93.92,54.37 94.13,54.58 95.91,54.58 96.93,53.57 99.85,53.57 102.92,56.64 J6.1
  L03_SIG1 w0.121: v2(81.84,34.33) 82.01,34.49 82.01,38.89 82.35,39.23 82.35,45.69 v1(79.91,48.13)
  BOTTOM w0.135: R193.1 90.1,49.39 89.96,49.25 v1(89.96,49.25) 88.39,49.25 87.93,49.71 87.58,49.71 86.56,50.72 82.5,50.72 v1(79.91,48.13)
TIMER_IO1: length 59.7
  TOP w0.102: U18.K20 81.39,35.64 81.39,35.64 81.39,36.67 81.36,36.7
  TOP w0.135: R19.1 89.51,51.21 v1(89.51,52.27) ; 81.36,36.7 81.36,38.91 80.95,39.32 80.95,39.88 81.74,40.67 81.74,42.98 v1(78.71,46)
  L03_SIG1 w0.121: v1(89.51,52.27) 89.82,51.96 90.31,51.96 90.44,52.09 90.44,53.38 90.73,53.67 93.38,53.67 93.65,53.4 93.65,52.34 93.77,52.22 94.01,52.22 94.13,52.34 94.13,53.4 94.25,53.52 94.49,53.52 94.61,53.4 94.61,52.34 94.73,52.22 94.98,52.22 95.1,52.34 95.1,53.4 95.27,53.57 95.71,53.57 96.36,52.92 104.45,52.92 104.73,53.2 104.73,53.37 104,54.1 104,54.27 104.17,54.44 104.34,54.44 105.08,53.71 105.25,53.71 105.42,53.88 105.42,54.05 104.69,54.78 104.69,54.95 104.86,55.12 105.03,55.12 105.76,54.39 105.93,54.39 106.79,55.25 J6.3
  BOTTOM w0.135: v1(78.71,46) 78.05,46.66 78.05,47.7 82.63,52.27 v1(89.51,52.27)
TIMER_IO2: length 59.1
  TOP w0.102: v2(81.46,34.92) 81.4,34.86 U18.J19
  TOP w0.135: J6.5 106.25,53.57 101.96,53.57 100.78,52.4 100.59,52.4 99.92,53.07 99.73,53.07 99.54,52.88 99.54,52.69 100.21,52.02 100.21,51.83 100.02,51.64 99.83,51.64 99.03,52.44 98.84,52.44 98.65,52.25 98.65,52.05 99.45,51.25 99.45,51.06 99.29,50.9 99.1,50.9 98.27,51.72 98.08,51.72 97.89,51.53 97.89,51.29 98.69,50.49 98.69,50.3 98.28,49.9 94.29,49.9 93.96,49.57 92.27,49.57 v1(91.69,49)
  L03_SIG1 w0.121: v2(81.46,34.92) 81.75,35.21 81.75,39 82.09,39.34 82.09,45.36 79.93,47.52 v1(78.92,47.52)
  BOTTOM w0.135: v1(78.92,47.52) 80.19,47.52 83.08,50.42 86.49,50.42 87.31,49.6 87.48,49.43 87.83,49.43 88.47,48.79 91.04,48.79 91.25,49 v1(91.69,49) 91.57,49.12 R192.1
TIMER_IO3: length 59.6
  TOP w0.102: v2(80.33,34.89) 80.59,34.64 80.61,34.64 U18.J18
  TOP w0.135: v1(87.27,50.62) 89.07,48.82 91.13,48.82 91.44,48.51 91.9,48.51 92.69,49.3 94.07,49.3 94.4,49.63 98.62,49.63 102.11,53.11 108.34,53.11 J6.7
  L03_SIG1 w0.102: v2(80.33,34.89) 80.33,36.53 80.51,36.7
  L03_SIG1 w0.121: v1(79.78,46.56) 79.78,45.77 79.45,45.44 78.56,45.44 78.16,45.03 78.16,42.82 78.61,42.37 79.98,42.37 81.07,41.28 81.07,40.76 80.41,40.1 80.41,38.9 80.51,38.79 80.51,36.7
  BOTTOM w0.135: v1(79.78,46.56) 79.04,46.56 78.49,47.12 78.49,47.7 82.63,51.84 86.06,51.84 v1(87.27,50.62) 87.92,49.98 88.05,49.98 R194.1
TIMER_IO4: length 27.6
  TOP w0.135: v1(90.93,53.06) 90.94,53.06 R20.1
  L03_SIG1 w0.121: v1(90.93,53.06) 92.33,53.06 93.47,51.92 95.81,51.92 96.45,52.56 105.04,52.56 107.88,55.4 113.17,55.4 J6.9
TIMER_IO4_R: length 30.5
  TOP w0.102: 81,36.7 81,36.42 81.17,36.25 81.17,35.64 U18.J20
  TOP w0.135: v1(79.04,45.02) 81.47,42.59 81.47,40.8 80.68,40.02 80.68,39.16 81,38.84 81,36.7 ; R20.2 90.9,50.41 90.32,49.83 88.82,49.83 87.55,51.1 86.94,51.1 86.28,50.44 v1(86.28,49.86)
  BOTTOM w0.135: v1(86.28,49.86) 85.45,49.86 85.19,49.61 85.19,47.89 86.11,46.97 86.11,45.57 85.56,45.02 v1(79.04,45.02)
TIMER_IO5: length 59.7
  TOP w0.102: 80.7,36.7 80.7,36.12 80.7,36.06 U18.J21
  TOP w0.135: v1(77.19,46.74) 77.19,46.23 79.25,44.17 79.48,44.17 81.15,42.5 81.15,40.94 80.41,40.21 80.41,38.89 80.7,38.61 80.7,36.7 ; R21.1 92.43,51.21 v1(92.43,52.27)
  L03_SIG1 w0.121: J6.11 115.45,55.15 115.11,55.15 109.4,55.15 105.92,51.67 93.03,51.67 v1(92.43,52.27)
  BOTTOM w0.135: v1(77.19,46.74) 77.19,47.27 82.62,52.7 89.51,52.7 89.8,52.99 90.24,52.99 90.96,52.27 v1(92.43,52.27)
TM4C129_TCK: length 5.1
  TOP w0.135: TP18.1 24.53,40.61 v1(24.43,40.71)
  BOTTOM w0.135: v1(24.43,40.71) 23.53,40.71 21.9,42.33 U37.100
TM4C129_TDI: length 3.8
  TOP w0.135: v1(21.77,40.71) 21.77,39.9 TP16.1
  BOTTOM w0.135: U37.98 21.1,41.38 v1(21.77,40.71)
TM4C129_TDO: length 3.6
  TOP w0.135: v1(20.62,41.71) 20.42,41.5 TP15.1
  BOTTOM w0.135: U37.97 20.7,41.79 v1(20.62,41.71)
TM4C129_TMS: length 4.2
  TOP w0.135: TP17.1 23.16,40.31 v1(22.91,40.56)
  BOTTOM w0.135: v1(22.91,40.56) 21.5,41.97 U37.99
TUSB_ADDR: length 3.9
  TOP w0.135: TP29.1 13.87,28.91 13.55,28.59 U20.5
TUSB_ID: length 3.9
  TOP w0.135: TP28.1 9.02,29.79 9.64,29.79 10.45,28.99 U20.9
TUSB_INT_N: length 2
  TOP w0.135: R110.1 14.14,29.68 13.45,28.99 U20.6
TUSB_OUT1: length 5.6
  TOP w0.135: R107.1 13.79,32.56 13.26,33.1 12.83,33.1 12.27,33.66 12.27,35.26 12.57,35.56 U15.2
TUSB_OUT1_R: length 3.5
  TOP w0.135: U20.7 11.92,29.96 12.34,30.38 R106.1 R107.2
TUSB_OUT2: length 7.3
  TOP w0.135: R104.1 9.45,32.49 11.67,34.7 R92.2 12.37,36.32 12.63,36.06 U15.1
TUSB_OUT2_R: length 3.6
  TOP w0.135: U20.8 11.52,29.67 10.9,30.29 R105.1 R104.2
TYPEC_CC1: length 15
  TOP w0.135: U20.1 11.52,22.54 v1(13.46,20.6)
  TOP w0.254: v1(17.78,18.67) 17.77,18.66 J10.A5
  L03_SIG1 w0.127: v1(17.78,18.67) 17.22,18.11 15.04,18.11 13.46,19.69 v1(13.46,20.6)
TYPEC_CC2: length 18.9
  TOP w0.135: v1(13.51,21.72) 11.92,23.31 U20.2
  L03_SIG1 w0.127: v1(13.51,21.72) 12.55,20.75 12.55,18.46 16.13,14.88 18.46,14.88 J10.B5
TYPEC_DN: length 15.3
  TOP w0.107: J10.A7 18.77,18.51 18.64,18.65 18.64,19.19 v1(19,19.56)
  L03_SIG1 w0.102: J10.B7 18.4,16.72 18.4,16.96 20.17,18.72 20.17,20.19 19.38,20.98 18.9,20.98 18.57,20.65 18.57,19.35 18.67,19.25 18.88,19.25 19,19.38 v1(19,19.56)
  BOTTOM w0.107: L3.2 18.4,22.79 18.09,22.48 18.09,21.99 18.32,21.75 D6.1 18.32,21.27 18.09,21.03 18.09,20.7 18.7,20.09 18.7,19.87 v1(19,19.56)
TYPEC_DP: length 15.3
  TOP w0.107: v1(18.06,19.56) 18.4,19.22 18.4,18.65 18.27,18.51 J10.A6
  L03_SIG1 w0.102: J10.B6 18.66,16.71 18.66,16.85 20.42,18.62 20.42,20.3 19.49,21.23 18.8,21.23 18.31,20.75 18.31,19.81 v1(18.06,19.56)
  BOTTOM w0.107: v1(18.06,19.56) 18.4,19.9 18.4,20.05 17.85,20.6 17.85,21.03 17.62,21.27 D7.1 17.62,21.75 17.85,21.99 17.85,22.48 17.55,22.79 L3.3
UART0_HDR_CTS#: length 54.5
  TOP w0.135: U8.6 109.28,49.18 v1(109.93,49.83)
  L03_SIG1 w0.121: v1(109.93,49.83) 112.26,49.83 116.24,53.81 137.07,53.81 139.67,56.41 153.52,56.41 J17.2
UART0_HDR_RTS#: length 51
  TOP w0.135: v1(107.57,50.83) 106.73,50.83 103.13,47.23 U8.12
  L03_SIG1 w0.121: J17.6 141.4,60.35 137.38,56.33 135.83,56.33 134.09,54.58 111.33,54.58 v1(107.57,50.83)
UART0_HDR_RXD: length 52.7
  TOP w0.135: v1(109.93,47.7) 109.46,47.23 U8.3
  L03_SIG1 w0.121: v1(109.93,47.7) 108.92,47.7 108.25,48.36 108.25,51.15 111.43,54.32 134.36,54.32 135.81,55.78 138.05,55.78 141.11,58.84 148.33,58.84 J17.5
UART0_HDR_TXD: length 55.2
  TOP w0.135: U8.9 103.66,49.18 105.94,51.46 v1(109.32,51.46)
  L03_SIG1 w0.121: v1(109.32,51.46) 111.93,54.07 136.82,54.07 140.85,58.1 150.13,58.1 J17.4
UART1_HDR_CTS#: length 59.4
  TOP w0.135: v1(114.27,42.32) 114.27,42.32 U12.6
  L03_SIG1 w0.121: J13.2 155.09,51.64 136.71,51.64 135.91,52.43 130.28,52.43 129.44,51.59 125.28,51.59 124.08,52.79 119.59,52.79 118.62,51.82 118.62,50.04 115.77,47.19 115.77,44.18 114.27,42.68 v1(114.27,42.32)
UART1_HDR_RTS#: length 52.8
  TOP w0.135: U12.12 102.98,40.37 106.6,43.99 v1(107.49,43.99)
  L03_SIG1 w0.121: J13.6 142.67,54 141.07,52.4 137.26,52.4 136.46,53.2 129.93,53.2 129.09,52.36 126.08,52.36 124.88,53.56 117.06,53.56 v1(107.49,43.99)
UART1_HDR_RXD: length 54.5
  TOP w0.135: U12.3 106.06,40.37 105.56,40.87 105.56,42.42 106.64,43.5 108.14,43.5 v1(108.64,43.99)
  L03_SIG1 w0.121: v1(108.64,43.99) 117.94,53.3 124.63,53.3 125.82,52.1 129.19,52.1 130.03,52.94 136.34,52.94 137.14,52.15 141.38,52.15 142.1,52.87 145.3,52.87 145.34,52.84 148.67,52.84 J13.5
UART1_HDR_TXD: length 57.6
  TOP w0.135: v1(109.78,43.99) 109.22,44.55 105.41,44.55 103.18,42.32 U12.9
  L03_SIG1 w0.121: v1(109.78,43.99) 118.83,53.05 124.37,53.05 125.57,51.85 129.32,51.85 130.16,52.69 136.16,52.69 136.96,51.89 150.27,51.89 J13.4
USB0_DN: length 128.3
  TOP w0.102: U18.AA17 87.02,33.73 87.63,33.73 87.64,33.74 87.74,33.74
  TOP w0.107: 87.74,33.74 88.1,33.74 89.34,34.98 91.47,34.98 92.21,35.72 94.66,35.72 v1(95.01,36.07)
  BOTTOM w0.107: v1(95.01,36.07) 95.29,35.79 95.68,35.79 95.94,35.53 95.94,18.06 90.47,12.6 85.42,12.6 83.35,14.66 78.78,14.66 75.85,11.73 67.53,11.73 66.83,11.02 40,11.02 38.89,12.14 38.89,19.1 40.51,20.72 40.51,24.13 39.44,25.2 30.71,25.2 29.71,24.2 22,24.2 19.56,26.64 18.28,26.64 18.09,26.44 18.09,26.14 18.4,25.83 L3.1
USB0_DP: length 128.3
  TOP w0.102: U18.AA16 87.04,33.5 87.73,33.5 87.74,33.51
  TOP w0.107: 87.74,33.51 88.19,33.51 89.43,34.75 91.57,34.75 92.3,35.48 94.68,35.48 v1(95.01,35.15)
  BOTTOM w0.107: v1(95.01,35.15) 94.89,35.28 94.89,35.43 95.02,35.56 95.58,35.56 95.7,35.44 95.7,18.16 90.38,12.83 85.52,12.83 83.45,14.9 78.68,14.9 75.75,11.96 67.44,11.96 66.73,11.26 40.1,11.26 39.12,12.24 39.12,19 40.74,20.62 40.74,24.23 39.54,25.44 30.62,25.44 29.62,24.43 22.1,24.43 19.66,26.87 18.19,26.87 17.85,26.54 17.85,26.14 17.55,25.83 L3.4
USB0_DRVVBUS: length 7
  TOP w0.102: 76.16,35.03 76.34,34.86 U18.B19
  TOP w0.135: TP21.1 72.65,35.86 73.96,35.86 74.29,36.19 75,36.19 76.16,35.03
USB0_ID: length 15
  TOP w0.102: U18.Y17 86.67,34.14 87.49,34.14 87.74,34.39
  TOP w0.135: R83.2 98.63,38.1 97.36,36.83 94.03,36.83 93.42,36.22 92.3,36.22 91.87,36.65 90,36.65 87.74,34.39
USB0_RCALIB: length 2.6
  TOP w0.102: v2(85.93,34.33) 85.89,34.3 U18.W17
  BOTTOM w0.135: v2(85.93,34.33) 86.44,34.84 86.44,35.47 86.97,36 R239.1
USB0_VBUS: length 154.6
  TOP w0.102: v2(85.93,34.89) U18.V18
  TOP w0.381: v1(39.27,26.01) R116.2 39.27,26.79 R118.2
  L03_SIG1 w0.254: v1(101.42,59.13) 101.42,59.64 100.56,60.5 85.48,60.5 83.32,58.35 78.51,58.35 75.02,61.84 v1(38.98,61.84) ; v2(85.93,34.89) 85.93,35.33 90.4,39.8 98.76,39.8 98.93,39.62 101.22,39.62 v1(103,41.4)
  BOTTOM w0.254: v1(101.42,59.13) 102.62,57.94 102.62,54.4 103.63,53.39 105.7,53.39 108.06,51.03 108.06,46.46 v1(103,41.4) ; v1(38.98,61.84) 38.15,61.01 38.15,54.31 40.01,52.45 40.01,50.93 35.55,46.47 35.55,44.34 39.88,40.01 40.57,40.01 41.1,39.47 41.1,27.84 v1(39.27,26.01)
USBC_SHIELD:
  vias: v1(13.34,13.59) v1(13.34,12.32) v1(14.61,13.59) v1(14.61,12.32) v1(15.88,13.59) v1(15.88,12.32) v1(22.99,13.59) v1(22.99,12.32) v1(24.26,13.59) v1(24.26,12.32) v1(25.53,12.32) v1(26.8,12.32)
USER_INTN: length 28.7
  TOP w0.102: U18.B9 77.11,30.14 76.67,30.14 76.33,29.8 76.31,29.8 76.25,29.73 76.23,29.73 76.16,29.67 76.05,29.67
  TOP w0.135: v1(63.98,30.13) 65.6,30.13 67.13,28.6 68.83,28.6 68.94,28.7 69.01,28.77 69.02,28.79 70.85,28.79 70.97,28.91 73.76,28.91 74.52,29.67 76.05,29.67 ; v1(62.08,38.71) 62.15,38.79 62.15,40.14 TP12.1 60.46,40.82 60.26,41.01 U13.5
  BOTTOM w0.135: v1(63.98,30.13) 63.98,36.8 v1(62.08,38.71)
VMON_MRN: length 21.1
  TOP w0.135: SW1.3 15.17,62.68 15.05,62.8 15.05,62.8 14.43,63.42 12.4,63.42 11.65,62.68 SW1.1 v1(10.44,61.62)
  BOTTOM w0.135: v1(10.44,61.62) 10.44,60.88 10.97,60.34 Q8.6 ; Q8.6 Q8.5 ; Q8.6 12.07,60.34 Q8.8 12.72,60.34 Q8.1 Q8.2 14.27,59.69 14.63,59.33 14.63,57.99 15.74,56.88 U27.1
  BOTTOM w0.152: v1(10.44,61.62) 10.44,62.34 C79.1 9.81,62.36 9.75,62.42 D5.1 R171.1
VMON_VSYS: length 28.8
  TOP w0.102: v2(79.42,31.9) 79.46,31.86 U18.G13
  L03_SIG1 w0.102: v2(79.42,31.9) 78.87,32.46 78.87,32.98 78.59,33.26 77.71,33.26 77.48,33.03 77.29,33.03
  L03_SIG1 w0.203: 77.29,33.03 77.28,33.02 74.6,33.02 73.89,32.31 70.89,32.31 69.33,30.75 68.21,30.75 67.76,31.2 67.76,33.05 v1(66.57,34.24)
  BOTTOM w0.203: C232.1 64.74,32.41 v1(66.57,34.24)
  BOTTOM w0.33: R255.1 64.58,26.82 C232.1
  BOTTOM w0.508: R262.2 R255.1
VPP_1V8: length 28.5
  TOP w0.203: U14.5 54,39.27 54,39.27
  TOP w0.254: 54.86,38.91 C38.1 57.15,38.91 58.75,37.31 v1(58.75,36.68) ; 54.86,38.91 54.2,38.91 U14.5 ; 54.86,38.91 54.86,38.91
  TOP w0.33: U18.E16 78.89,33.82 v2(78.9,33.82)
  L03_SIG1 w0.254: v2(78.9,33.82) 73.62,33.82 73.05,34.39 69.37,34.39 69.01,34.75 64.29,34.75 62.36,36.68 v1(58.75,36.68)
VPP_1V8_REG_EN: length 40.1
  TOP w0.135: J22.2 36.17,9.88 38.59,12.3 38.59,19.8 41.01,22.21 41.01,34.25 v1(40.59,34.67)
  TOP w0.33: U14.3 50.18,36.82 49.6,36.24 R90.2 v1(49.07,35.48)
  L03_SIG1 w0.121: v1(40.59,34.67) 48.26,34.67 v1(49.07,35.48)
VPP_1V8_REG_EN_ON: length 4.6
  TOP w0.135: R593.1 33.64,12.76 32.46,11.58 J22.1
VSYS_3V3: length 258.4
  TOP w0.254: U19.18 C46.1 C43.1 140.18,36.32 v1(140.16,36.35) ; R89.2 64.4,38.08 64.19,37.86 64.19,37.31 63.93,37.06 C41.1 ; U7.30 135.01,48.33 134.51,48.83 C14.1 133.98,49.34 v1(133.91,49.4) ; U7.18 C7.1 C6.1 140.18,55.37 v1(140.16,55.4) ; U13.8 58.76,43.09 C29.1 ; U5.6 58.41,48.25 C15.1 58.03,48.23 v1(57.85,48.06) ; U16.6 26.62,34.64 v1(26.57,34.7) ; R80.1 45.54,39.75 46.36,40.56 54.1,40.56 56.58,43.04 v1(56.58,45.52) ; v1(33.35,34.57) 33.28,34.64 C45.1 U16.3 ; U4.24 31.84,52.72 32.13,53.01 ; U4.23 33.34,51.65 33.5,51.82 ; v1(159.87,24.54) C59.1 159.44,25.15 159.06,24.77 U22.10 ; v1(133.99,30.35) 133.98,30.34 C54.1 134.51,29.78 135.01,29.28 U19.30 ; R5.2 v1(71.06,58.2)
  TOP w0.305: C41.1 63.39,36.8 U17.8 ; C21.1 51.03,47.37 v1(50.78,47.62)
  TOP w0.33: U8.14 C24.1 v1(99.84,45.37) ; U25.1 68.09,16.37 68.33,16.13 C74.1 67.95,15.62 67.61,15.29 v1(67.61,15.19) ; v1(115.95,48.13) 115.95,48.14 R32.2 ; v1(34.77,53.19) 34.87,53.09 C8.1 ; U3.4 C9.2 v1(111.98,52.51) ; U12.14 C37.1 v1(99.84,38.49) ; U2.2 82.27,48.01 82.78,48.51 82.78,48.77 83.2,49.2 C12.1 83.21,50.35 C10.1 ; 126.19,48.11 126.29,48.01 C16.2 C13.1 v1(126.83,49.45) ; v1(52.05,47.62) 51.92,47.5 C22.1 ; C43.1 v1(139.54,35.26) ; C6.1 v1(139.54,54.31) ; v1(84.76,49.2) 84.51,48.95 R37.2 ; C29.1 v1(58.17,43.1)
  TOP w0.381: v1(69.55,49.86) 69.03,49.35 R36.2 ; v1(44.2,35.43) 44.17,35.4 R112.2 ; R88.1 66.6,37.11 65.63,38.08 R89.2 ; R10.2 84.24,56.61 84.25,56.62 v1(84.33,56.62) ; R1.2 18.52,60.06 v1(18.52,60.07) ; R95.1 139.49,35.31 v1(139.54,35.26) ; v1(34.3,58.6) 34.29,58.6 34.28,58.59 R3.2 ; U9.1 10.37,43.86 10.59,43.64 ; R164.2 65.43,8.74 65.13,8.43 v1(65.1,8.43) ; v1(67.13,38.68) 67.31,38.51 R82.1 ; R4.2 v1(25.58,58.57) ; U6.6 126.11,48.19 126.19,48.11 ; R593.2 34.68,13.97 35.71,12.94 v1(35.71,12.19) ; v1(98.27,42.09) 98.25,42.09 97.57,42.76 R588.2 ; v1(91.77,38.46) 91.99,38.46 92.61,39.08 R590.2
  TOP w0.508: R73.1 136.22,41.05 135.89,40.72 v1(135.89,40.71) ; v1(141.66,21.62) 141.66,21.69 141.66,21.7 R136.1 ; v1(140.18,21.62) 140.18,21.69 140.19,21.7 R135.1 ; R68.1 v1(132.21,43.74) ; 49.64,50.04 49.36,49.77 R35.1 49.36,47.64 49.64,47.37 C27.1 ; R91.1 5.55,37.35 5.18,37.72 v1(5.16,37.72) ; R43.2 94.29,48.87 v1(94.31,48.9) ; v1(97.33,48.87) 97.34,48.87 R45.2 ; v1(142.23,16.52) 139.14,13.44 v1(139.14,12.47) ; R40.2 89.5,48.19 v1(89.51,48.18) 89.66,48.18 89.67,48.19 R41.2 ; v1(64.94,38.79) 64.94,38.15 R89.2 ; R134.1 v1(136.22,21.64) ; R12.1 v1(135.95,54.49) ; R79.1 v1(7.01,40.77) ; C10.1 v1(83.23,51.3) ; v1(98.81,17.55) 98.81,15.19 100.5,13.5 R163.1 ; C40.1 R80.1 ; v1(95.81,48.9) 95.81,48.89 R44.2 ; v1(86.99,49.21) 87.13,49.07 R39.2 ; R129.1 v1(132.21,24.69)
  L03_SIG1 w0.254: v1(67.61,15.19) 67.61,20.78 v1(68.58,21.74)
  L04_PWR1 w0.508: v1(67.61,15.19) 66.45,14.02 66.45,12.5 65.61,11.66 ; v1(33.35,34.57) 30.63,34.57 ; v1(99.82,17.55) 99.82,20.47
  L05_GND2 w0.508: v1(143.31,20.7) 142.23,19.62 v1(142.23,16.52)
  BOTTOM w0.135: 132.99,45.87 v1(132.99,45.89)
  BOTTOM w0.178: C259.1 U42.1
  BOTTOM w0.203: C218.1 120.88,29.36 ; C122.1 120.88,39.98 ; U33.5 122.15,42.78 121.97,42.95 ; U39.4 121.14,31.29 ; C219.1 119.87,29.36
  BOTTOM w0.254: U46.2 140.24,12.47 140.24,12.47 C270.1 v1(139.14,12.47) ; v1(133.91,49.4) 133.99,49.32 C93.1 ; U40.1 C166.1 v1(111.55,33.91) ; v1(111.17,24.51) C248.1 110.92,25.33 109.71,25.33 U40.17 ; v1(96.95,52.12) 96.96,52.12 C90.1 U30.10 ; v1(115.95,48.13) 115.95,47.62 116.36,47.22 C103.1 117.14,47.04 117.88,47.04 118.06,47.22 U32.2 ; v1(103.64,28.79) 103.63,28.8 C209.1 104.4,29.54 104.6,29.34 U40.30 ; v1(112.7,29.77) 112.64,29.71 110.58,29.71 110.46,29.84 U40.8 ; U46.8 v1(142.23,16.52) ; U32.15 C106.1
  BOTTOM w0.33: v1(168.05,16.46) C265.2 166.15,16.46 165.82,16.79 U44.5 ; v1(75.13,48.26) 75.46,47.93 C94.1 U31.5 ; v1(126.82,44.81) 126.31,45.31 C106.1 ; v1(68.58,21.74) 68.83,21.49 C259.1 ; C159.1 140.16,35.52 C152.1 ; C54.1 133.98,30.34 v1(133.99,30.35) ; U43.5 140.92,20.93 C258.1 143.08,20.93 v1(143.31,20.7) 143.31,20.09 143.06,19.84 R275.2 ; 159.1,42.54 159.13,42.57 C112.2 160.15,42.57 160.15,42.57 v1(160.21,42.57) ; C86.1 C84.1 ; C152.1 139.85,35.56 v1(139.54,35.26) ; C152.1 140.21,36.3 v1(140.16,36.35) ; U34.5 140.35,40.16 140.68,39.83 C119.1 142.6,39.83 142.88,39.55 v1(142.88,38.86) 142.1,38.86 R236.2
  BOTTOM w0.381: R210.1 v1(178.94,56.25) ; v1(133.93,41.48) 133.85,41.39 R230.1 ; R227.1 141.35,41.47 U34.5 ; R224.2 43.3,42.06 43.64,42.39 43.64,48.52 v1(45.58,50.46) ; R258.1 v1(179.05,35.61) ; v1(144.02,41.48) 143.94,41.48 143.93,41.47 R226.1 ; v1(142.47,22.43) 142.48,22.42 R266.1 ; R229.1 135.37,41.39 v1(135.46,41.48) ; R264.1 v1(147.34,22.42) ; R170.2 v1(27.61,59.36) ; v1(146.18,41.48) 146.17,41.47 R225.1 ; R268.1 v1(135.47,22.42) ; 159.1,42.54 U35.1 ; v1(133.99,30.35) 132.13,30.35 131.73,29.95 131.73,27.25 132.13,26.85 v1(132.99,26.85) 132.99,26.82 R254.1 ; R218.1 132.99,45.87 ; R265.1 v1(145.51,22.42) ; C84.1 139.85,54.61 v1(139.54,54.31) ; R269.1 v1(133.94,22.42)
  BOTTOM w0.508: R167.1 166.56,62.4 v1(166.55,62.41) 166.54,62.4 R166.1 ; R169.1 R168.1 v1(175.9,63.76) ; v1(92.74,34.9) FB4.1 91.25,35.52 v1(91.82,36.09) ; R282.1 v1(175.98,10.97) ; R285.1 v1(171.48,10.97) ; R183.2 v1(79.78,54.03) ; R252.2 v1(157,28.63) ; R257.2 v1(157,31.93) ; v1(64.94,38.79) 64.94,38.51 65.45,38.01 R238.1 R237.1 ; v1(70.97,39.27) 71.83,38.4 FB3.1 ; R220.2 v1(161.34,38.44) ; R223.2 v1(161.34,41.53) ; R284.1 v1(172.98,10.97) ; v1(44.2,35.43) 44.2,39.57 42.55,41.22 R224.2 ; R181.2 v1(75.16,55.38) ; R201.2 23.02,50.44 23.6,49.87 23.6,47.93 22.83,47.17 v1(21.67,47.17) ; R283.1 v1(174.48,10.97)
  vias: v1(9.63,41.96) v1(10.49,42.8) v1(33.5,53.19) v1(36.98,12.19) v1(50.78,50.16) v1(50.78,48.9) v1(52.05,50.16) v1(52.05,48.9) v1(53.32,50.16) v1(53.32,48.9) v1(53.32,47.62) v1(54.59,50.16) v1(54.59,48.9) v1(54.59,47.62) v1(56.58,48.06) v1(56.58,46.79) v1(57.85,46.79) v1(57.85,45.52) v1(59.12,46.79) v1(59.12,45.52) v1(88.87,21.56) v1(89.51,21.97) v1(99.09,59.54) v1(100.36,59.54) v1(100.36,58.27) v1(116.59,42.42) v1(116.59,41.15) v1(116.59,39.88) v1(116.59,31.7) v1(116.59,30.43) v1(116.59,29.16) v1(117.86,42.42) v1(117.86,41.15) v1(117.86,39.88) v1(117.86,31.7) v1(117.86,30.43) v1(117.86,29.16)
